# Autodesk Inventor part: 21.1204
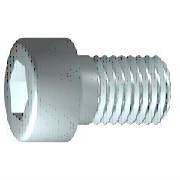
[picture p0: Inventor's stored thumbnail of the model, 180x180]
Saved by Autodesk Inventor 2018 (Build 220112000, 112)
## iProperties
Created: 2006-02
Part Number: 21.1204
Material: Steel, Mild
Description: M8 x 25 SHCS
Document SubType Name: Modeling
Standard: DIN 7984
Designer: Andy Moles
Standards Organization: DIN
Language: en-US
Size Designation: M8 x 25
Categories: <MemberInstance><Categories><Category DisplayName="Fasteners" InternalName="e4da775c-781d-43d5-af7c-5136215cf5a6" Mnemonic="FSTN"><Category DisplayName="Bolts"
Density: 7.85 g/cm^3
Mass: 14.2203 g
Surface Area: 11.4333 cm^2
Volume: 1.81151 cm^3
Vendor: S
Appearance: Zinc
Author: Andy Moles
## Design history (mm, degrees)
sketch "Sketch1"
  geometry: L1 (0.467, 0)-(25, 0); L2 (25, 0)-(25, 4); L3 (25, 4)-(1, 4); L4 (1, 4)-(0.233, 4); L5 (0.233, 4)-(0, 4); L6 (0, 4)-(0, 6.5); L7 (0, 6.5)-(-5, 6.5); L8 (-5, 6.5)-(-5, 2.887); L9 (-5, 2.887)-(-1.2, 2.887); L10 (-1.2, 2.887)-(0.467, 0); L11 (-8, 0)-(34, 0) reference; L12 (0, -0.65)-(0, 8.45) reference; L13 (1, 4)-(0, 4)
  constraints: 22 end point, 6 parallel, 2 collinear, 2 perpendicular, 1 horizontal, 1 point on line
  dimensions: "d1" = 24 distance from line of L3.end L2 (= GEL); "d2" = 0.76691 distance of L4.end L3.end (computed from GAL); "d3" = 5 distance between parallel lines of L8 L6 (= KOH); "d4" = 3.8 distance of L8.end L9.end (= INTI); "d5" = 60 deg angle of L10 L1; "d6" = 8 diameter of L3 L1 (= GD); "d7" = 8 diameter of L5 L1 (= BDM); "d8" = 5.7735 diameter of L9 L1 (= 1.1547 x SW); "d9" = 13 diameter of L7 L1 (= KOD); "d26" = 25 distance between parallel lines of L12 L2 (= NLG)
revolve "Body" sketch "Sketch1" stored, may be unused: angle "d10" = 90 deg
sketch "Sketch2"
  geometry: L1 (0, -7.8)-(0, 10.4) reference; L2 (-7.8, 0)-(10.4, 0) reference; L3 (2.887, 0)-(1.443, -2.5); L4 (1.443, -2.5)-(-1.443, -2.5); L5 (-1.443, -2.5)-(-2.887, 0); L6 (-2.887, 0)-(-1.443, 2.5); L7 (-1.443, 2.5)-(1.443, 2.5); L8 (1.443, 2.5)-(2.887, 0); 2 further points
  constraints: 12 end point, 1 coincident, 1 horizontal alignment, 1 point on line, 12 other
extrude "Slot" join sketch "Sketch2" stored distance "d11" = 10; taper "d12" = 0 deg
workplane "Work Plane1"
body "Solid1"
fillet "Fillet1" dims "d17" = 0.8 (= RR)
feature "Thread" dims "d13" = 25, "d14" = 0
chamfer "Chamfer1" distance "d15" = 0.76681 (= -0.5 x SPD + 0.5 x GD); stored, may be unused: second distance "d16" = 0.76681 (= GUL), angle "d27" = 45 deg
other parameters: "GD" = 8 (= NND) [user parameter; used in 2 equation terms], "NLG" = 25 [user parameter; used in 1 equation term], "GEL" = 24 [user parameter; used in 1 equation term], "KOD" = 13 [user parameter; used in 1 equation term], "KOH" = 5 [user parameter; used in 1 equation term], "INTI" = 3.8 [user parameter; used in 1 equation term], "GAL" = 0.76681 (= 0.61345 x PTC) [user parameter; used in 1 equation term], "GUL" = 0.76681 (= 0.61345 x PTC) [user parameter; used in 1 equation term], "BDM" = 8 (= NND) [user parameter; used in 1 equation term], "SW" = 5 [user parameter; used in 2 equation terms], "RR" = 0.8 [user parameter; used in 1 equation term], "SPD" = 6.46637 (= NND - 1.2269 x PTC) [user parameter; used in 1 equation term], "d19" = 0, "d28" = 0, "d29" = 0, "TOA" = 30 deg [user parameter], "GD1" = 6.46637 (= THREADDIA - 1.2269 x PTC) [user parameter], "THREADDIA" = 8 [user parameter; used in 1 equation term], "FAWI" = 45 deg [user parameter], "ANG" = 120 deg [user parameter], "TPU" = 8 (computed from PTC) [user parameter], "PTC" = 1.25 [user parameter; used in 5 equation terms], "NND" = 8 [user parameter; used in 3 equation terms], "E0" = 5.775 (= 1.155 x SW) [user parameter]
